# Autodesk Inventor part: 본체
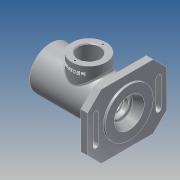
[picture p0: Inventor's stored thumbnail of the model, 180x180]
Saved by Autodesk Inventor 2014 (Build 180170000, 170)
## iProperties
Created: 2017-10
Part Number: 본체
Material: 알루미늄 6061
Document SubType Name: Modeling
Designer: kb542-14
Density: 2.71 g/cm^3
Appearance: 알루미늄 - 평지
Mass: 738.969 g
Surface Area: 652.224 cm^2
Volume: 272.682 cm^3
Author: kb542-14
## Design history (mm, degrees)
sketch "스케치1"
  geometry: L1 (-57.5, 0)-(57.5, 0); L2 (-57.5, 21)-(-48.5, 21); L3 (-48.5, 21)-(-48.5, 24); L4 (-48.5, 24)-(-45.5, 24); L5 (-45.5, 24)-(-45.5, 20); L6 (-45.5, 20)-(-36.5, 20); L7 (-36.5, 20)-(-36.5, 17.5); L8 (-36.5, 17.5)-(-33.25, 17.5); L9 (-33.25, 17.5)-(-33.25, 18.5); L10 (-33.25, 18.5)-(-31.5, 18.5); L11 (-31.5, 18.5)-(-31.5, 17.5); L12 (-31.5, 17.5)-(-20.5, 17.5); L13 (-20.5, 17.5)-(-20.5, 26); L14 (-20.5, 26)-(17.5, 26); L15 (17.5, 26)-(17.5, 17.5); L16 (17.5, 17.5)-(28.2, 17.5); L17 (28.5, 17.2)-(28.5, 16.5); L18 (28.5, 16.5)-(31.2, 16.5); L19 (34.2, 13.5)-(34.2, 10); L20 (34.2, 10)-(36.9, 10); L21 (36.9, 10)-(36.9, 12.2); L22 (37.2, 12.5)-(43.5, 12.5); L23 (57.5, 22)-(57.5, 35); L24 (57.5, 35)-(44.5, 35); L25 (44.5, 31)-(-57.5, 31); L26 (-57.5, 31)-(-57.5, 21); L27 (44.5, 31)-(44.5, 35); L28 (43.5, 12.5)-(44.2, 12.904); L29 (44.2, 12.904)-(44.2, 14.062); L30 (45.966, 16.797)-(57.5, 22); A1 r 3 centre (47.2, 14.062) between (45.966, 16.797) and (44.2, 14.062); A2 r 3 centre (31.2, 13.5) between (34.2, 13.5) and (31.2, 16.5); A3 r 0.3 centre (37.2, 12.2) between (37.2, 12.5) and (36.9, 12.2); A4 r 0.3 centre (28.2, 17.2) between (28.5, 17.2) and (28.2, 17.5); 6 further points
  constraints: 60 end point, 26 parallel, 8 point on circle, 8 point on line, 8 tangent, 4 centre point, 2 equal radius, 2 vertical alignment, 1 coincident, 1 horizontal, 1 midpoint, 1 perpendicular
  dimensions: "d0" = 62 diameter of L25 L1; "d1" = 48 diameter of L4 L1; "d2" = 42 diameter of L2 L1; "d4" = 40 diameter of L6 L1; "d5" = 35 diameter of L8 L1; "d6" = 37 diameter of L10 L1; "d7" = 35 diameter of L12 L1; "d8" = 52 diameter of L14 L1; "d9" = 35 diameter of L16 L1; "d10" = 33 diameter of L18 L1; "d11" = 20 diameter of L20 L1; "d13" = 115 distance between parallel lines of L23 L26; "d14" = 3 distance between parallel lines of L5 L3; "d15" = 12 distance between parallel lines of L5 L26; "d16" = 38 distance between parallel lines of L15 L13; "d17" = 21 distance between parallel lines of L26 L7; "d18" = 1.75 distance between parallel lines of L11 L9; "d19" = 26 distance between parallel lines of L26 L11; "d20" = 11 distance between parallel lines of L13 L11; "d21" = 14 distance from line of L22.end L23; "d23" = 70 diameter of L24 L1; "d24" = 13 distance between parallel lines of L27 L23; "d26" = 2.7 distance between parallel lines of L21 L19; "d27" = 11 distance between parallel lines of L17 L15; "d28" = 44 diameter of L23.start L1; "d31" = 7.3 distance from line of point (44.2, 16) L21; "d32" = 32 diameter of point (44.2, 16) L1; "d35" = 25 diameter of L22 L1; "d36" = 0.7 distance from line of L22.end L29; "d37" = 30 deg angle of L28 L22; "d82" = 3 radius of A1; "d83" = 0.3 radius of A3
revolve "회전1" sketch "스케치1" stored, may be unused: angle "d38" = 90 deg
node "작업 평면1"
sketch "스케치2"
  geometry: L1 (-58, -47)-(58, -47); L2 (58, -47)-(58, 47); L3 (58, 47)-(-58, 47); L4 (-58, 47)-(-58, -47); L5 (-58, -47)-(58, 47); L6 (58, -47)-(-58, 47); C1 r 35 at (0, 0) reference; C2 r 22 at (0, 0) reference; 3 further points
  constraints: 12 end point, 3 midpoint, 2 parallel, 1 coincident, 1 horizontal, 1 perpendicular
  dimensions: "d40" = 94 distance between parallel lines of L3 L1; "d41" = 116 distance between parallel lines of L2 L4
extrude "돌출1" join sketch "스케치2" distance "d42" = 10; taper "d43" = 0 deg
chamfer "모따기1" distance "d44" = 20; stored, may be unused: second distance "d45" = 2, angle "d46" = 45 deg
sketch "스케치3"
  geometry: L1 (94, 0)-(94, 76) reference; L2 (27, 84)-(67, 84); L3 (27, 88)-(67, 88); L4 (67, 80)-(27, 80); C1 r 31 at (47, 38) reference; A1 r 4 centre (27, 84) between (27, 88) and (27, 80); A2 r 4 centre (67, 84) between (67, 80) and (67, 88); 1 further point
  constraints: 8 end point, 4 point on circle, 4 tangent, 2 centre point, 1 midpoint, 1 parallel, 1 perpendicular, 1 vertical alignment
  dimensions: "d47" = 40 distance of L2.start L2.end; "d48" = 4 radius of A1; "d49" = 46 distance of point (47, 84) C1.centre
extrude "돌출2" cut sketch "스케치3" stored distance "d50" = 10; taper "d51" = 0 deg
feature "스레드1" dims "d52" = 9, "d53" = 0
node "작업 평면2"
sketch "스케치4"
  geometry: L1 (-57.5, -31)-(-57.5, 31) reference; C1 r 25 at (-1.5, 0); 2 further points
  constraints: 1 centre point, 1 horizontal alignment, 1 midpoint
  dimensions: "d55" = 50 diameter of C1; "d56" = 56 distance from line of C1.centre L1
extrude "돌출3" join sketch "스케치4" stored distance "d57" = 10; taper "d58" = 0 deg
sketch "스케치5"
  geometry: C1 r 25 at (0, 0) reference; C2 r 16 at (0, 0); 1 further point
  constraints: 1 centre point, 1 coincident
  dimensions: "d59" = 32 diameter of C2
extrude "돌출4" cut sketch "스케치5" stored distance "d60" = 10; taper "d61" = 0 deg
chamfer "모따기2" distance "d62" = 1; stored, may be unused: second distance "d63" = 2, angle "d64" = 45 deg
sketch "스케치6" dims "d65" = 41
  geometry: C1 r 25 at (0, 0) reference; C2 r 17 at (0, 0) reference; 3 further points
  constraints: 2 vertical alignment, 1 coincident, 2 other
hole "구멍1" sketch "스케치6" at (0, 20.5) diameter "d66" = 2.459; stored, may be unused: countersink angle "d70" = 90 deg, drill point angle "d72" = 118 deg; dims "d67" = 6, "d68" = 4, "d69" = 2, "d71" = 8
fillet "모깎기1" dims "d76" = 3
node "작업 평면3"
sketch "스케치7"
  geometry: L1 (-25, 0)-(25, 0) reference; L2 (-56, -78)-(-56, -16) reference; 2 further points
  constraints: 1 other
  dimensions: "d77" = 10 distance from line of point (0, -10) L1; "d78" = 56 distance from line of point (0, -10) L2
feature "엠보싱1" sketch "스케치7" dims "d2" = 42, "d79" = 0.5, "d80" = 0
fillet "모깎기2" dims "d81" = 3
chamfer "모따기3" distance "d84" = 1; stored, may be unused: second distance "d85" = 2, angle "d86" = 45 deg
node "솔리드1"
mirror "대칭1"
pattern_circular "원형 패턴1" dims angle "d74" = 360 deg
node "투영된 루프1"
other parameters: "d39" = -3, "d54" = 47
